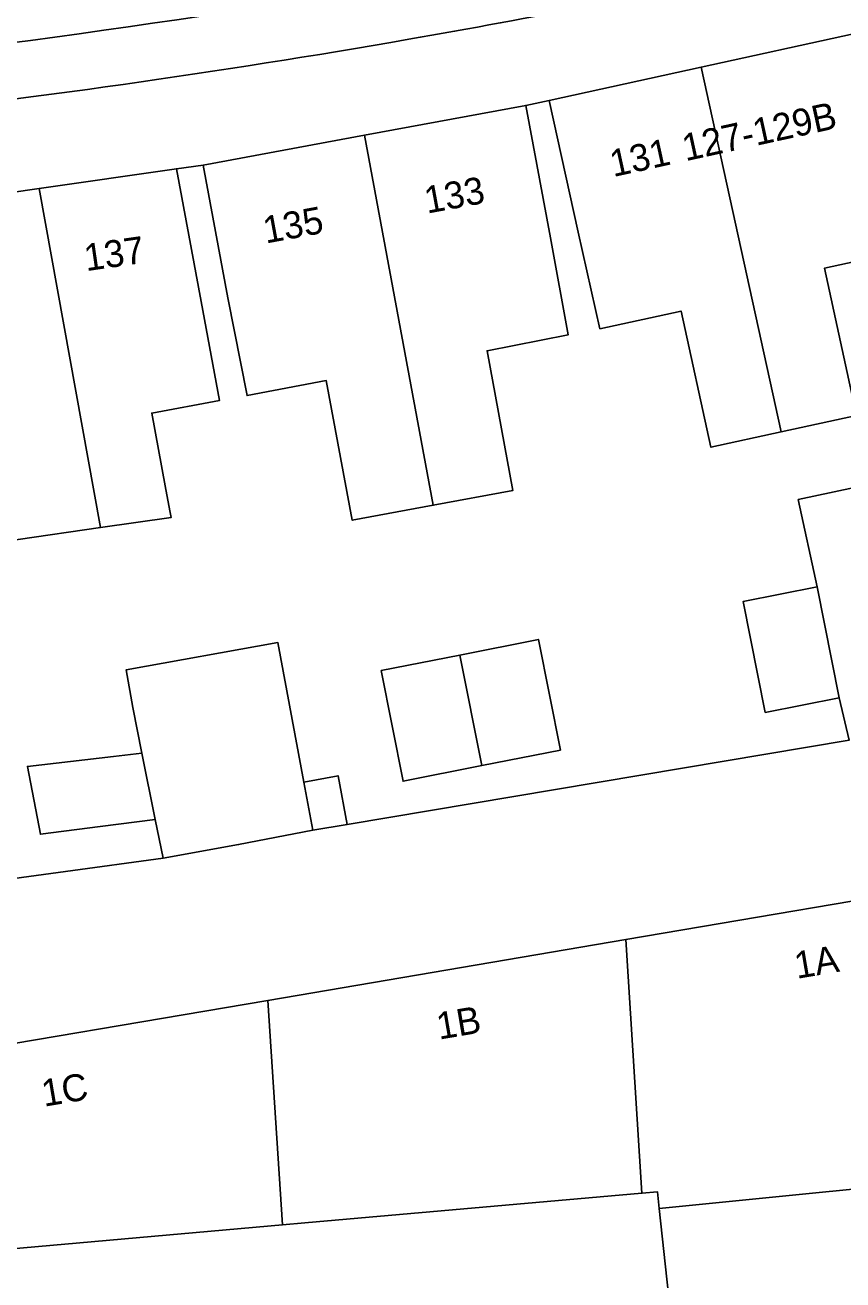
# Model space of a CAD drawing. Extents: x 158086 to 159499, y 382904 to 383981.
# Drawn here: x 158724.99 to 158755.27, y 383089.86 to 383136.37 of the extents above; entities that cross this region are included whole.
import ezdxf

# ---------------------------------------------------------------- set-up
doc = ezdxf.new("R2010")
doc.units = 0
for name, color, linetype in [('IMGEO_Berm_open', 7, 'Continuous'), ('IMGEO_Erf', 7, 'Continuous'), ('IMGEO_Fietspad_gesloten', 7, 'Continuous'), ('IMGEO_Pand', 7, 'Continuous'), ('IMGEO_Pand_nummerreeks', 7, 'Continuous'), ('IMGEO_Voetpad_open', 7, 'Continuous')]:
    doc.layers.add(name, color=color, linetype=linetype)

msp = doc.modelspace()

# ---------------------------------------------------------------- linework, layer by layer
at = {"layer": 'IMGEO_Berm_open'}
msp.add_arc((158680.46, 383472.252), 339.403, 276.33743, 281.27294, dxfattribs=at)
at = {"layer": 'IMGEO_Erf'}
for points in [[(158757.43, 383127.98), (158754.589, 383127.358), (158755.782, 383121.907), (158752.992, 383121.296), (158750.385, 383120.725), (158749.28, 383125.773), (158746.274, 383125.115), (158745.466, 383128.692), (158744.396, 383133.576), (158743.528, 383133.396), (158744.441, 383128.481), (158745.099, 383124.894), (158742.094, 383124.299), (158743.055, 383119.125), (158740.102, 383118.577), (158737.099, 383118.019), (158736.137, 383123.198), (158733.207, 383122.641), (158732.494, 383126.261), (158731.581, 383131.177), (158730.588, 383131.047), (158731.501, 383126.131), (158732.183, 383122.454), (158729.677, 383121.989), (158730.179, 383119.293), (158730.35, 383118.372), (158730.396, 383118.126), (158727.774, 383117.745), (158721.67, 383116.857)], [(158722.852, 383104.508), (158730.094, 383105.488), (158729.807, 383106.921), (158727.766, 383106.661), (158725.552, 383106.379), (158725.073, 383108.895), (158728.261, 383109.265), (158729.313, 383109.389), (158728.976, 383111.077), (158728.725, 383112.469), (158734.347, 383113.482), (158735.308, 383108.31), (158736.577, 383108.545), (158736.913, 383106.739), (158755.51, 383109.866), (158755.138, 383111.437), (158752.399, 383110.894), (158751.583, 383115.01), (158754.322, 383115.552), (158753.618, 383118.787), (158764.689, 383121.143)]]:
    msp.add_lwpolyline(points, dxfattribs=at)
for points in [[(158764.689, 383121.143), (158753.618, 383118.787), (158754.322, 383115.552), (158755.138, 383111.437), (158755.51, 383109.866), (158736.913, 383106.739), (158735.639, 383106.525), (158732.895, 383105.995), (158730.094, 383105.488), (158722.852, 383104.508), (158723.039, 383102.3), (158716.884, 383101.677), (158718.069, 383090.31), (158718.605, 383090.373), (158717.917, 383097.44), (158720.691, 383097.961), (158733.981, 383100.221), (158747.231, 383102.474), (158760.476, 383104.727), (158767.506, 383105.922)], [(158744.81, 383109.499), (158741.896, 383108.921), (158738.987, 383108.345), (158738.174, 383112.445), (158741.083, 383113.021), (158743.997, 383113.599)], [(158776.04, 383094.375), (158775.916, 383095.471), (158771.783, 383094.846), (158761.199, 383093.782), (158748.475, 383092.503), (158750.034, 383078.044), (158747.892, 383067.794), (158729.739, 383071.533), (158724.841, 383072.542), (158724.899, 383072.159), (158725.782, 383066.336), (158726.467, 383061.823), (158731.365, 383060.817), (158746.016, 383057.807), (158748.125, 383068.073), (158781.694, 383061.178), (158782.229, 383063.783), (158787.714, 383062.657), (158786.952, 383058.944), (158791.767, 383057.954), (158793.9, 383068.563), (158789.002, 383069.567), (158786.505, 383070.079)]]:
    msp.add_lwpolyline(points, close=True, dxfattribs=at)
at = {"layer": 'IMGEO_Fietspad_gesloten'}
for centre, radius, start, end in [((158680.46, 383472.252), 339.403, 276.33743, 281.27294), ((158680.517, 383471.92), 341.158, 279.90418, 281.05997), ((158681.402, 383467.354), 336.507, 276.24219, 279.88938)]:
    msp.add_arc(centre, radius, start, end, dxfattribs=at)
at = {"layer": 'IMGEO_Pand'}
for points in [[(158750.03, 383134.81), (158752.992, 383121.296), (158755.782, 383121.907), (158754.589, 383127.358), (158757.43, 383127.98), (158756.734, 383131.16), (158755.664, 383136.044)], [(158750.03, 383134.81), (158744.396, 383133.576), (158745.466, 383128.692), (158746.274, 383125.115), (158749.28, 383125.773), (158750.385, 383120.725), (158752.992, 383121.296)], [(158737.555, 383132.287), (158740.102, 383118.577), (158743.055, 383119.125), (158742.094, 383124.299), (158745.099, 383124.894), (158744.441, 383128.481), (158743.528, 383133.396)], [(158737.555, 383132.287), (158731.581, 383131.177), (158732.494, 383126.261), (158733.207, 383122.641), (158736.137, 383123.198), (158737.099, 383118.019), (158740.102, 383118.577)], [(158731.501, 383126.131), (158730.588, 383131.047), (158725.512, 383130.313), (158727.774, 383117.745), (158730.396, 383118.126), (158730.35, 383118.372), (158730.179, 383119.293), (158729.677, 383121.989), (158732.183, 383122.454)], [(158719.678, 383129.47), (158721.67, 383116.857), (158727.774, 383117.745), (158725.512, 383130.313)], [(158754.322, 383115.552), (158751.583, 383115.01), (158752.399, 383110.894), (158755.138, 383111.437)], [(158729.313, 383109.389), (158729.807, 383106.921), (158730.094, 383105.488), (158732.895, 383105.995), (158735.639, 383106.525), (158735.308, 383108.31), (158734.347, 383113.482), (158728.725, 383112.469), (158728.976, 383111.077)], [(158741.083, 383113.021), (158741.896, 383108.921), (158744.81, 383109.499), (158743.997, 383113.599)], [(158741.083, 383113.021), (158738.174, 383112.445), (158738.987, 383108.345), (158741.896, 383108.921)], [(158729.313, 383109.389), (158728.261, 383109.265), (158725.073, 383108.895), (158725.552, 383106.379), (158727.766, 383106.661), (158729.807, 383106.921)], [(158735.639, 383106.525), (158736.913, 383106.739), (158736.577, 383108.545), (158735.308, 383108.31)], [(158760.476, 383104.727), (158747.231, 383102.474), (158747.833, 383093.069), (158748.409, 383093.119), (158748.475, 383092.503), (158761.199, 383093.782)], [(158747.231, 383102.474), (158733.981, 383100.221), (158734.518, 383091.902), (158735.351, 383091.976), (158747.833, 383093.069)], [(158733.981, 383100.221), (158720.691, 383097.961), (158717.917, 383097.44), (158718.605, 383090.373), (158722.692, 383090.85), (158734.518, 383091.902)], [(158748.475, 383092.503), (158748.409, 383093.119), (158747.833, 383093.069), (158735.351, 383091.976), (158734.518, 383091.902), (158722.692, 383090.85), (158724.841, 383072.542), (158729.739, 383071.533), (158747.892, 383067.794), (158750.034, 383078.044)]]:
    msp.add_lwpolyline(points, close=True, dxfattribs=at)
at = {"layer": 'IMGEO_Voetpad_open'}
msp.add_lwpolyline([(158709.195, 383131.31), (158709.008, 383128.354), (158713.924, 383128.638), (158719.678, 383129.47), (158725.512, 383130.313), (158730.588, 383131.047), (158731.581, 383131.177), (158737.555, 383132.287), (158743.528, 383133.396), (158744.396, 383133.576), (158750.03, 383134.81), (158755.664, 383136.044)], dxfattribs=at)
for centre, radius, start, end in [((158680.517, 383471.92), 341.158, 279.90418, 281.05997), ((158681.402, 383467.354), 336.507, 276.24219, 279.88938)]:
    msp.add_arc(centre, radius, start, end, dxfattribs=at)

# ---------------------------------------------------------------- texts
at = {"layer": 'IMGEO_Pand_nummerreeks'}
for s, rotation, p in [('127-129B', 12.3543, (158749.446, 383131.324)), ('131', 12.3543, (158746.768, 383130.738)), ('133', 10.522, (158739.874, 383129.382)), ('135', 10.522, (158733.9, 383128.273)), ('137', 8.2277, (158727.246, 383127.249)), ('1A', 9.651, (158753.57, 383101.016)), ('1B', 9.651, (158740.316, 383098.762)), ('1C', 9.651, (158725.689, 383096.275))]:
    msp.add_text(s, height=1, rotation=rotation, dxfattribs=at).set_placement(p)

doc.saveas('drawing.dxf')
